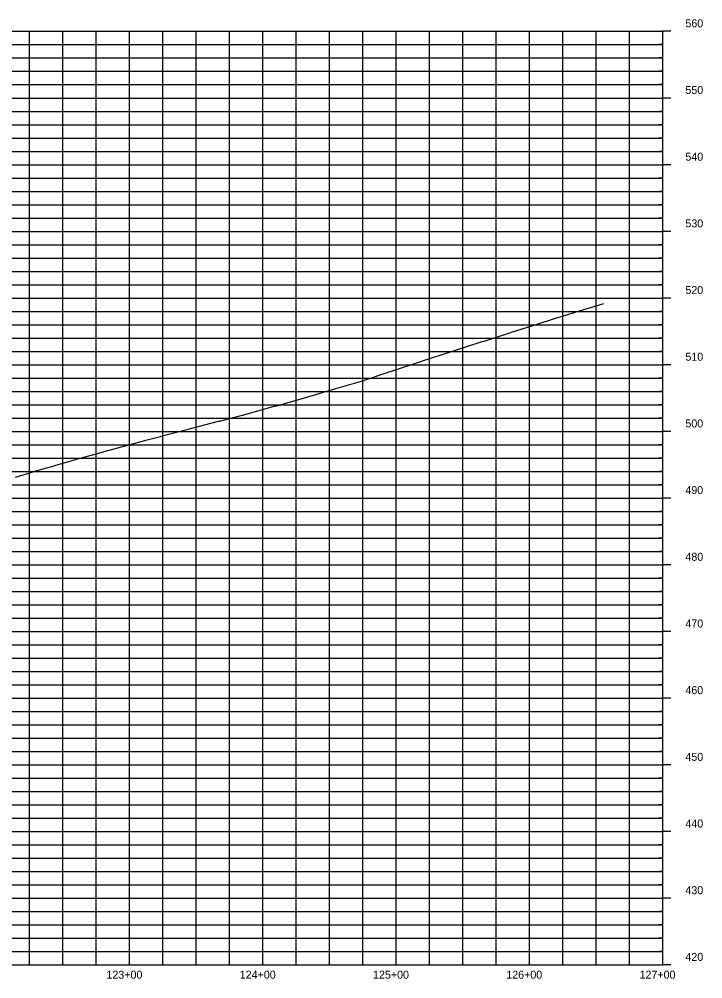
# Model space of a CAD drawing. Extents: x 1054002 to 1056762, y 395173 to 397393.
# Drawn here: x 1056249 to 1056762, y 396673 to 397393 of the extents above; entities that cross this region are included whole.
import ezdxf

# ---------------------------------------------------------------- set-up
doc = ezdxf.new("R2010")
doc.units = 0
for name, color, linetype in [('R_Axis_Annotation', 7, 'Continuous'), ('R_Exist Surface', 7, 'Continuous'), ('R_Grid', 7, 'Continuous'), ('R_Grid Annot', 7, 'Continuous'), ('R_Grid_Minor', 7, 'Continuous')]:
    doc.layers.add(name, color=color, linetype=linetype)

msp = doc.modelspace()

# ---------------------------------------------------------------- linework, layer by layer
at = {"layer": 'R_Exist Surface'}
msp.add_lwpolyline([(1056246.6, 397049.21), (1056260.64, 397053.44), (1056261.28, 397053.63), (1056276.38, 397057.98), (1056276.83, 397058.11), (1056291.9, 397062.45), (1056292.38, 397062.59), (1056312.69, 397068.16), (1056313.1, 397068.27), (1056333.62, 397073.9), (1056333.82, 397073.96), (1056345.36, 397077.01), (1056355.57, 397079.71), (1056355.75, 397079.76), (1056377.32, 397085.46), (1056377.88, 397085.61), (1056399.03, 397091.07), (1056399.65, 397091.22), (1056420.74, 397096.67), (1056421.4, 397096.85), (1056441.77, 397102.48), (1056442.48, 397102.67), (1056462.8, 397108.29), (1056463.59, 397108.53), (1056484.55, 397114.75), (1056485.28, 397114.97), (1056506.29, 397121.2), (1056506.98, 397121.43), (1056528.58, 397128.56), (1056529.53, 397128.87), (1056550.87, 397135.91), (1056552.13, 397136.32), (1056573.81, 397143.32), (1056575.25, 397143.79), (1056596.76, 397150.73), (1056598.2, 397151.17), (1056617.47, 397157.32), (1056618.92, 397157.76), (1056638.18, 397163.92), (1056651.12, 397168.01), (1056652.07, 397168.3), (1056665.04, 397172.41), (1056665.95, 397172.69), (1056667.33, 397173.09), (1056688, 397179.3)], dxfattribs=at)
at = {"layer": 'R_Grid'}
for p, q in [((1054032.29, 397383.41), (1056732.29, 397383.41)), ((1054032.29, 397383.41), (1056732.29, 397383.41)), ((1056332.29, 396683.41), (1056332.29, 397383.41)), ((1056432.29, 396683.41), (1056432.29, 397383.41)), ((1056532.29, 396683.41), (1056532.29, 397383.41)), ((1056632.29, 396683.41), (1056632.29, 397383.41)), ((1056732.29, 396683.41), (1056732.29, 397383.41)), ((1054032.29, 397333.41), (1056732.29, 397333.41)), ((1054032.29, 397283.41), (1056732.29, 397283.41)), ((1054032.29, 397233.41), (1056732.29, 397233.41)), ((1054032.29, 397183.41), (1056732.29, 397183.41)), ((1054032.29, 397133.41), (1056732.29, 397133.41)), ((1054032.29, 397083.41), (1056732.29, 397083.41)), ((1054032.29, 397033.41), (1056732.29, 397033.41)), ((1054032.29, 396983.41), (1056732.29, 396983.41)), ((1054032.29, 396933.41), (1056732.29, 396933.41)), ((1054032.29, 396883.41), (1056732.29, 396883.41)), ((1054032.29, 396833.41), (1056732.29, 396833.41)), ((1054032.29, 396783.41), (1056732.29, 396783.41)), ((1054032.29, 396733.41), (1056732.29, 396733.41)), ((1054032.29, 396683.41), (1056732.29, 396683.41))]:
    msp.add_line(p, q, dxfattribs=at)
at = {"layer": 'R_Grid Annot'}
for p, q in [((1056738.29, 397383.41), (1056732.29, 397383.41)), ((1056738.29, 397383.41), (1056732.29, 397383.41)), ((1056732.29, 397373.41), (1056729.29, 397373.41)), ((1056732.29, 397363.41), (1056729.29, 397363.41)), ((1056732.29, 397353.41), (1056729.29, 397353.41)), ((1056732.29, 397343.41), (1056729.29, 397343.41)), ((1056738.29, 397333.41), (1056732.29, 397333.41)), ((1056732.29, 397323.41), (1056729.29, 397323.41)), ((1056732.29, 397313.41), (1056729.29, 397313.41)), ((1056732.29, 397303.41), (1056729.29, 397303.41)), ((1056732.29, 397293.41), (1056729.29, 397293.41)), ((1056738.29, 397283.41), (1056732.29, 397283.41)), ((1056732.29, 397273.41), (1056729.29, 397273.41)), ((1056732.29, 397263.41), (1056729.29, 397263.41)), ((1056732.29, 397253.41), (1056729.29, 397253.41)), ((1056732.29, 397243.41), (1056729.29, 397243.41)), ((1056738.29, 397233.41), (1056732.29, 397233.41)), ((1056732.29, 397223.41), (1056729.29, 397223.41)), ((1056732.29, 397213.41), (1056729.29, 397213.41)), ((1056732.29, 397203.41), (1056729.29, 397203.41)), ((1056732.29, 397193.41), (1056729.29, 397193.41)), ((1056738.29, 397183.41), (1056732.29, 397183.41)), ((1056732.29, 397173.41), (1056729.29, 397173.41)), ((1056732.29, 397163.41), (1056729.29, 397163.41)), ((1056732.29, 397153.41), (1056729.29, 397153.41)), ((1056732.29, 397143.41), (1056729.29, 397143.41)), ((1056738.29, 397133.41), (1056732.29, 397133.41)), ((1056732.29, 397123.41), (1056729.29, 397123.41)), ((1056732.29, 397113.41), (1056729.29, 397113.41)), ((1056732.29, 397103.41), (1056729.29, 397103.41)), ((1056732.29, 397093.41), (1056729.29, 397093.41)), ((1056738.29, 397083.41), (1056732.29, 397083.41)), ((1056732.29, 397073.41), (1056729.29, 397073.41)), ((1056732.29, 397063.41), (1056729.29, 397063.41)), ((1056732.29, 397053.41), (1056729.29, 397053.41)), ((1056732.29, 397043.41), (1056729.29, 397043.41)), ((1056738.29, 397033.41), (1056732.29, 397033.41)), ((1056732.29, 397023.41), (1056729.29, 397023.41)), ((1056732.29, 397013.41), (1056729.29, 397013.41)), ((1056732.29, 397003.41), (1056729.29, 397003.41)), ((1056732.29, 396993.41), (1056729.29, 396993.41)), ((1056738.29, 396983.41), (1056732.29, 396983.41)), ((1056732.29, 396973.41), (1056729.29, 396973.41)), ((1056732.29, 396963.41), (1056729.29, 396963.41)), ((1056732.29, 396953.41), (1056729.29, 396953.41)), ((1056732.29, 396943.41), (1056729.29, 396943.41)), ((1056738.29, 396933.41), (1056732.29, 396933.41)), ((1056732.29, 396923.41), (1056729.29, 396923.41)), ((1056732.29, 396913.41), (1056729.29, 396913.41)), ((1056732.29, 396903.41), (1056729.29, 396903.41)), ((1056732.29, 396893.41), (1056729.29, 396893.41)), ((1056738.29, 396883.41), (1056732.29, 396883.41)), ((1056732.29, 396873.41), (1056729.29, 396873.41)), ((1056732.29, 396863.41), (1056729.29, 396863.41)), ((1056732.29, 396853.41), (1056729.29, 396853.41)), ((1056732.29, 396843.41), (1056729.29, 396843.41)), ((1056738.29, 396833.41), (1056732.29, 396833.41)), ((1056732.29, 396823.41), (1056729.29, 396823.41)), ((1056732.29, 396813.41), (1056729.29, 396813.41)), ((1056732.29, 396803.41), (1056729.29, 396803.41)), ((1056732.29, 396793.41), (1056729.29, 396793.41)), ((1056738.29, 396783.41), (1056732.29, 396783.41)), ((1056732.29, 396773.41), (1056729.29, 396773.41)), ((1056732.29, 396763.41), (1056729.29, 396763.41)), ((1056732.29, 396753.41), (1056729.29, 396753.41)), ((1056732.29, 396743.41), (1056729.29, 396743.41)), ((1056738.29, 396733.41), (1056732.29, 396733.41)), ((1056732.29, 396723.41), (1056729.29, 396723.41)), ((1056732.29, 396713.41), (1056729.29, 396713.41)), ((1056732.29, 396703.41), (1056729.29, 396703.41)), ((1056732.29, 396693.41), (1056729.29, 396693.41)), ((1056738.29, 396683.41), (1056732.29, 396683.41))]:
    msp.add_line(p, q, dxfattribs=at)
at = {"layer": 'R_Grid_Minor'}
for p, q in [((1056257.29, 396683.41), (1056257.29, 397383.41)), ((1056282.29, 396683.41), (1056282.29, 397383.41)), ((1056307.29, 396683.41), (1056307.29, 397383.41)), ((1056357.29, 396683.41), (1056357.29, 397383.41)), ((1056382.29, 396683.41), (1056382.29, 397383.41)), ((1056407.29, 396683.41), (1056407.29, 397383.41)), ((1056457.29, 396683.41), (1056457.29, 397383.41)), ((1056482.29, 396683.41), (1056482.29, 397383.41)), ((1056507.29, 396683.41), (1056507.29, 397383.41)), ((1056557.29, 396683.41), (1056557.29, 397383.41)), ((1056582.29, 396683.41), (1056582.29, 397383.41)), ((1056607.29, 396683.41), (1056607.29, 397383.41)), ((1056657.29, 396683.41), (1056657.29, 397383.41)), ((1056682.29, 396683.41), (1056682.29, 397383.41)), ((1056707.29, 396683.41), (1056707.29, 397383.41)), ((1054032.29, 397373.41), (1056732.29, 397373.41)), ((1054032.29, 397363.41), (1056732.29, 397363.41)), ((1054032.29, 397353.41), (1056732.29, 397353.41)), ((1054032.29, 397343.41), (1056732.29, 397343.41)), ((1054032.29, 397323.41), (1056732.29, 397323.41)), ((1054032.29, 397313.41), (1056732.29, 397313.41)), ((1054032.29, 397303.41), (1056732.29, 397303.41)), ((1054032.29, 397293.41), (1056732.29, 397293.41)), ((1054032.29, 397273.41), (1056732.29, 397273.41)), ((1054032.29, 397263.41), (1056732.29, 397263.41)), ((1054032.29, 397253.41), (1056732.29, 397253.41)), ((1054032.29, 397243.41), (1056732.29, 397243.41)), ((1054032.29, 397223.41), (1056732.29, 397223.41)), ((1054032.29, 397213.41), (1056732.29, 397213.41)), ((1054032.29, 397203.41), (1056732.29, 397203.41)), ((1054032.29, 397193.41), (1056732.29, 397193.41)), ((1054032.29, 397173.41), (1056732.29, 397173.41)), ((1054032.29, 397163.41), (1056732.29, 397163.41)), ((1054032.29, 397153.41), (1056732.29, 397153.41)), ((1054032.29, 397143.41), (1056732.29, 397143.41)), ((1054032.29, 397123.41), (1056732.29, 397123.41)), ((1054032.29, 397113.41), (1056732.29, 397113.41)), ((1054032.29, 397103.41), (1056732.29, 397103.41)), ((1054032.29, 397093.41), (1056732.29, 397093.41)), ((1054032.29, 397073.41), (1056732.29, 397073.41)), ((1054032.29, 397063.41), (1056732.29, 397063.41)), ((1054032.29, 397053.41), (1056732.29, 397053.41)), ((1054032.29, 397043.41), (1056732.29, 397043.41)), ((1054032.29, 397023.41), (1056732.29, 397023.41)), ((1054032.29, 397013.41), (1056732.29, 397013.41)), ((1054032.29, 397003.41), (1056732.29, 397003.41)), ((1054032.29, 396993.41), (1056732.29, 396993.41)), ((1054032.29, 396973.41), (1056732.29, 396973.41)), ((1054032.29, 396963.41), (1056732.29, 396963.41)), ((1054032.29, 396953.41), (1056732.29, 396953.41)), ((1054032.29, 396943.41), (1056732.29, 396943.41)), ((1054032.29, 396923.41), (1056732.29, 396923.41)), ((1054032.29, 396913.41), (1056732.29, 396913.41)), ((1054032.29, 396903.41), (1056732.29, 396903.41)), ((1054032.29, 396893.41), (1056732.29, 396893.41)), ((1054032.29, 396873.41), (1056732.29, 396873.41)), ((1054032.29, 396863.41), (1056732.29, 396863.41)), ((1054032.29, 396853.41), (1056732.29, 396853.41)), ((1054032.29, 396843.41), (1056732.29, 396843.41)), ((1054032.29, 396823.41), (1056732.29, 396823.41)), ((1054032.29, 396813.41), (1056732.29, 396813.41)), ((1054032.29, 396803.41), (1056732.29, 396803.41)), ((1054032.29, 396793.41), (1056732.29, 396793.41)), ((1054032.29, 396773.41), (1056732.29, 396773.41)), ((1054032.29, 396763.41), (1056732.29, 396763.41)), ((1054032.29, 396753.41), (1056732.29, 396753.41)), ((1054032.29, 396743.41), (1056732.29, 396743.41)), ((1054032.29, 396723.41), (1056732.29, 396723.41)), ((1054032.29, 396713.41), (1056732.29, 396713.41)), ((1054032.29, 396703.41), (1056732.29, 396703.41)), ((1054032.29, 396693.41), (1056732.29, 396693.41))]:
    msp.add_line(p, q, dxfattribs=at)

# ---------------------------------------------------------------- texts
at = {"layer": 'R_Axis_Annotation'}
for s, p in [('560', (1056749.3, 397386.41)), ('560', (1056749.3, 397386.41)), ('550', (1056749.3, 397336.41)), ('540', (1056749.3, 397286.41)), ('530', (1056749.3, 397236.41)), ('520', (1056749.3, 397186.41)), ('510', (1056749.3, 397136.41)), ('500', (1056749.3, 397086.41)), ('490', (1056749.3, 397036.41)), ('480', (1056749.3, 396986.41)), ('470', (1056749.3, 396936.41)), ('460', (1056749.3, 396886.41)), ('450', (1056749.3, 396836.41)), ('440', (1056749.3, 396786.41)), ('430', (1056749.3, 396736.41)), ('420', (1056749.3, 396686.41)), ('123+00', (1056314.89, 396673.06)), ('124+00', (1056414.89, 396673.06)), ('125+00', (1056514.89, 396673.06)), ('126+00', (1056614.89, 396673.06)), ('127+00', (1056714.89, 396673.06))]:
    msp.add_text(s, height=6, dxfattribs=at).set_placement(p)

doc.saveas('drawing.dxf')
